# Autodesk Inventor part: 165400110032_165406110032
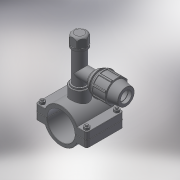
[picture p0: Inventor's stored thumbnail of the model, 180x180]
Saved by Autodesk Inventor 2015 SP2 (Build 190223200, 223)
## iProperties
Created: 2017-05
Part Number: 165400110032_165406110032
Material: Generic
Description: PLASSON TAPPER FOR PE+PVC PIPE 110-32
Document SubType Name: Modeling
Designer: KIM
Density: 1 g/cm^3
Appearance: Default
Author: KIM
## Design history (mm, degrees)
derived "16540.ipt"
feature "Solid1::16540.ipt"
feature "Solid2::16540.ipt"
tag "TaggingFeature1"
body "Solid1"
other parameters: "d0" = 121, "d1" = 165, "d2" = 55, "d4" = 116, "d5" = 0, "d6" = 8.25, "d7" = 165, "d8" = 0.1, "d10" = 0, "d11" = 1.1, "d14" = 50.6376, "d20" = 1.1, "d23" = 1.1, "d36" = 13, "d37" = 10.4, "d38" = 63, "d39" = 0, "d40" = 3, "d41" = 5, "d42" = 0, "d43" = 8, "d44" = 3, "d45" = 0, "d46" = 1.1, "d51" = 91, "d52" = 38.952, "d53" = 25, "d54" = 0, "d55" = 32, "d57" = 0, "d58" = 118.8, "d60" = 0, "d62" = 13, "d63" = 10.4, "d66" = 95.2, "d67" = 32, "d68" = 9.08333, "d69" = 21.8, "d70" = 64, "d71" = 48, "d72" = 1.55714, "d73" = 51.2, "d74" = 120 deg, "d75" = 48, "d76" = 10 deg, "d77" = 57.6, "d78" = 32.7, "d79" = 71, "d80" = 25.6, "d81" = 109, "d82" = 7.1, "d87" = 15.57143, "d90" = 59.52, "d91" = 35 deg, "d92" = 17.5 deg, "d94" = 0, "d96" = 360 deg, "d98" = 0.64, "d99" = 78.1, "d100" = 35.0568, "d101" = 135 deg, "d102" = 1.28, "d105" = 3.2, "d106" = 0, "d107" = 0.1, "d108" = 35.0568, "d109" = 42.8472, "d111" = 26.4, "d112" = 6.6, "d113" = 3.63333, "d116" = 0, "d117" = 38, "d118" = 21.8, "d119" = 0, "d121" = 132, "d122" = 59, "B_" = 32, "G_" = 38.952, "A_" = 91, "L_" = 165, "L_1" = 116, "l_2" = 25, "d_1" = 32, "E_" = 64, "l_" = 71, "H_" = 109, "H_1" = 59, "H_2" = 132
